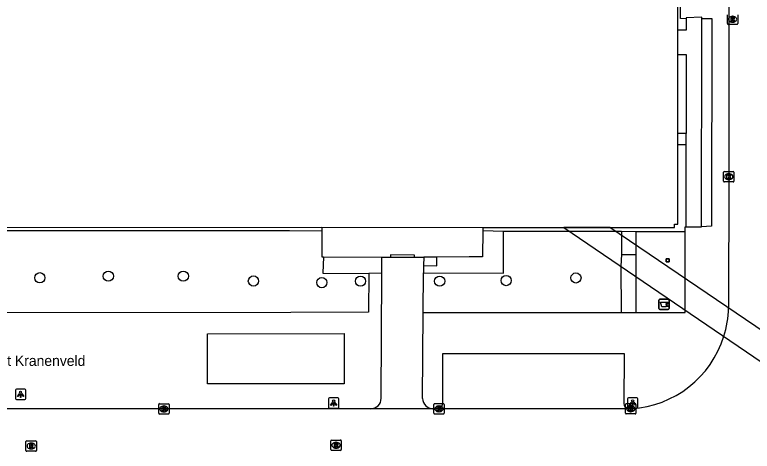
# Model space of a CAD drawing. Extents: x 161477 to 163040, y 383680 to 384868.
# Drawn here: x 161890.4 to 161961.2, y 384115.1 to 384157 of the extents above; entities that cross this region are included whole.
import ezdxf

# ---------------------------------------------------------------- set-up
doc = ezdxf.new("R2010")
doc.units = 0
for name, color, linetype in [('IMGEO_Afvalbak', 7, 'Continuous'), ('IMGEO_Boom', 7, 'Continuous'), ('IMGEO_Dek', 7, 'Continuous'), ('IMGEO_Groenvoorziening', 7, 'Continuous'), ('IMGEO_Kolk', 7, 'Continuous'), ('IMGEO_Lage_trafo', 7, 'Continuous'), ('IMGEO_Lichtpunt', 7, 'Continuous'), ('IMGEO_Openbare_ruimte_label', 7, 'Continuous'), ('IMGEO_Pand', 7, 'Continuous'), ('IMGEO_Pijler', 7, 'Continuous'), ('IMGEO_Rijbaan_lokaal_gesloten', 7, 'Continuous'), ('IMGEO_Rijbaan_lokaal_open', 7, 'Continuous'), ('IMGEO_Rioolput', 7, 'Continuous'), ('IMGEO_Terreindeel_halfverhard', 7, 'Continuous'), ('IMGEO_Voetpad_gesloten', 7, 'Continuous'), ('IMGEO_Voetpad_op_trap', 7, 'Continuous'), ('IMGEO_Voetpad_open', 7, 'Continuous')]:
    doc.layers.add(name, color=color, linetype=linetype)

msp = doc.modelspace()

# ---------------------------------------------------------------- linework, layer by layer
at = {"layer": 'IMGEO_Afvalbak'}
for p, q in [((161952.272, 384128.83), (161952.272, 384129.63)), ((161952.272, 384129.63), (161952.272, 384128.83)), ((161952.372, 384129.73), (161953.162, 384129.73)), ((161953.162, 384129.73), (161952.372, 384129.73)), ((161953.262, 384129.63), (161953.262, 384128.83)), ((161953.262, 384128.83), (161953.262, 384129.63)), ((161953.162, 384128.73), (161952.372, 384128.73)), ((161952.372, 384128.73), (161953.162, 384128.73))]:
    msp.add_line(p, q, dxfattribs=at)
msp.add_lwpolyline([(161952.415, 384129.444), (161953.119, 384129.444), (161952.97, 384128.974), (161952.564, 384128.974), (161952.415, 384129.444)], dxfattribs=at)
for centre, start, end in [((161952.372, 384129.63), 90, 180), ((161952.372, 384129.63), 90, 180), ((161953.162, 384129.63), 0, 90), ((161953.162, 384129.63), 360, 90), ((161952.372, 384128.83), 180, 270), ((161952.372, 384128.83), 180, 270), ((161953.162, 384128.83), 270, 0), ((161953.162, 384128.83), 270, 0)]:
    msp.add_arc(centre, 0.1, start, end, dxfattribs=at)
at = {"layer": 'IMGEO_Boom'}
for centre in [(161892.822, 384131.776), (161899.399, 384131.933), (161906.601, 384131.933), (161937.613, 384131.503), (161944.308, 384131.754), (161913.334, 384131.463), (161919.911, 384131.306), (161923.619, 384131.452), (161931.22, 384131.452)]:
    msp.add_circle(centre, 0.489, dxfattribs=at)
at = {"layer": 'IMGEO_Dek'}
msp.add_lwpolyline([(161947.548, 384136.601), (161943.149, 384136.604), (161969.026, 384119.003), (161969.032, 384122.037)], close=True, dxfattribs=at)
at = {"layer": 'IMGEO_Groenvoorziening'}
for points in [[(161870.773, 384136.302), (161876.802, 384136.301), (161879.272, 384136.301), (161916.787, 384136.298), (161919.889, 384136.28)], [(161929.655, 384132.234), (161937.363, 384132.218), (161937.349, 384136.252)], [(161937.349, 384136.252), (161943.684, 384136.24), (161948.093, 384136.231), (161948.689, 384136.23)], [(161950.049, 384136.227), (161954.784, 384136.218)], [(161920.067, 384133.782), (161920.015, 384132.225), (161924.432, 384132.187)], [(161952.977, 384133.298), (161952.983, 384133.587), (161953.272, 384133.581), (161953.266, 384133.292), (161952.977, 384133.298)], [(161953.265, 384129.319), (161953.27, 384129.041), (161952.992, 384129.036), (161952.987, 384129.314), (161953.265, 384129.319)]]:
    msp.add_lwpolyline(points, dxfattribs=at)
at = {"layer": 'IMGEO_Kolk'}
for p, q in [((161958.484, 384141.044), (161958.484, 384141.896)), ((161958.559, 384141.97), (161959.411, 384141.97)), ((161959.485, 384141.896), (161959.485, 384141.044)), ((161958.995, 384141.19), (161958.97, 384141.19)), ((161958.972, 384141.75), (161958.997, 384141.75)), ((161959.411, 384140.97), (161958.559, 384140.97)), ((161904.241, 384118.765), (161904.241, 384119.617)), ((161904.316, 384119.691), (161905.168, 384119.691)), ((161904.729, 384119.471), (161904.754, 384119.471)), ((161905.242, 384119.617), (161905.242, 384118.765)), ((161930.657, 384118.77), (161930.657, 384119.622)), ((161930.732, 384119.696), (161931.584, 384119.696)), ((161931.145, 384119.476), (161931.17, 384119.476)), ((161931.658, 384119.622), (161931.658, 384118.77)), ((161949.069, 384118.774), (161949.069, 384119.626)), ((161949.144, 384119.7), (161949.996, 384119.7)), ((161949.557, 384119.48), (161949.582, 384119.48)), ((161950.07, 384119.626), (161950.07, 384118.774)), ((161905.168, 384118.691), (161904.316, 384118.691)), ((161904.752, 384118.911), (161904.727, 384118.911)), ((161931.584, 384118.696), (161930.732, 384118.696)), ((161931.168, 384118.916), (161931.143, 384118.916)), ((161949.996, 384118.7), (161949.144, 384118.7)), ((161949.58, 384118.92), (161949.555, 384118.92))]:
    msp.add_line(p, q, dxfattribs=at)
for points in [[(161958.484, 384141.044), (161958.484, 384141.896)], [(161958.559, 384141.97), (161959.411, 384141.97)], [(161959.485, 384141.896), (161959.485, 384141.044)], [(161958.805, 384141.67), (161958.928, 384141.67), (161958.928, 384141.519), (161959.058, 384141.67), (161959.222, 384141.67), (161959.076, 384141.519), (161959.229, 384141.27), (161959.077, 384141.27), (161958.992, 384141.434), (161958.928, 384141.367), (161958.928, 384141.27), (161958.805, 384141.27), (161958.805, 384141.67)], [(161959.411, 384140.97), (161958.559, 384140.97)], [(161904.241, 384118.765), (161904.241, 384119.617)], [(161904.316, 384119.691), (161905.168, 384119.691)], [(161904.562, 384119.391), (161904.685, 384119.391), (161904.685, 384119.24), (161904.815, 384119.391), (161904.979, 384119.391), (161904.833, 384119.24), (161904.986, 384118.991), (161904.834, 384118.991), (161904.749, 384119.155), (161904.685, 384119.088), (161904.685, 384118.991), (161904.562, 384118.991), (161904.562, 384119.391)], [(161905.242, 384119.617), (161905.242, 384118.765)], [(161930.657, 384118.77), (161930.657, 384119.622)], [(161930.732, 384119.696), (161931.584, 384119.696)], [(161930.978, 384119.396), (161931.101, 384119.396), (161931.101, 384119.245), (161931.231, 384119.396), (161931.395, 384119.396), (161931.249, 384119.245), (161931.402, 384118.996), (161931.25, 384118.996), (161931.165, 384119.16), (161931.101, 384119.093), (161931.101, 384118.996), (161930.978, 384118.996), (161930.978, 384119.396)], [(161931.658, 384119.622), (161931.658, 384118.77)], [(161949.069, 384118.774), (161949.069, 384119.626)], [(161949.144, 384119.7), (161949.996, 384119.7)], [(161949.39, 384119.4), (161949.513, 384119.4), (161949.513, 384119.249), (161949.643, 384119.4), (161949.807, 384119.4), (161949.661, 384119.249), (161949.814, 384119), (161949.662, 384119), (161949.577, 384119.164), (161949.513, 384119.097), (161949.513, 384119), (161949.39, 384119), (161949.39, 384119.4)], [(161950.07, 384119.626), (161950.07, 384118.774)], [(161905.168, 384118.691), (161904.316, 384118.691)], [(161931.584, 384118.696), (161930.732, 384118.696)], [(161949.996, 384118.7), (161949.144, 384118.7)]]:
    msp.add_lwpolyline(points, dxfattribs=at)
for centre, start, end in [((161958.561, 384141.894), 91.55205, 178.44795), ((161958.561, 384141.894), 91.55205, 178.44795), ((161959.409, 384141.894), 1.55205, 88.44795), ((161959.409, 384141.894), 1.55205, 88.44795), ((161958.561, 384141.046), 181.55205, 268.44795), ((161958.561, 384141.046), 181.55205, 268.44795), ((161959.409, 384141.046), 271.55205, 358.44795), ((161959.409, 384141.046), 271.55205, 358.44795), ((161904.318, 384119.615), 91.55205, 178.44795), ((161904.318, 384119.615), 91.55205, 178.44795), ((161905.166, 384119.615), 1.55205, 88.44795), ((161905.166, 384119.615), 1.55205, 88.44795), ((161930.734, 384119.62), 91.55205, 178.44795), ((161930.734, 384119.62), 91.55205, 178.44795), ((161931.582, 384119.62), 1.55205, 88.44795), ((161931.582, 384119.62), 1.55205, 88.44795), ((161949.146, 384119.624), 91.55205, 178.44795), ((161949.146, 384119.624), 91.55205, 178.44795), ((161949.994, 384119.624), 1.55205, 88.44795), ((161949.994, 384119.624), 1.55205, 88.44795), ((161904.318, 384118.767), 181.55205, 268.44795), ((161904.318, 384118.767), 181.55205, 268.44795), ((161905.166, 384118.767), 271.55205, 358.44795), ((161905.166, 384118.767), 271.55205, 358.44795), ((161930.734, 384118.772), 181.55205, 268.44795), ((161930.734, 384118.772), 181.55205, 268.44795), ((161931.582, 384118.772), 271.55205, 358.44795), ((161931.582, 384118.772), 271.55205, 358.44795), ((161949.146, 384118.776), 181.55205, 268.44795), ((161949.146, 384118.776), 181.55205, 268.44795), ((161949.994, 384118.776), 271.55205, 358.44795), ((161949.994, 384118.776), 271.55205, 358.44795)]:
    msp.add_arc(centre, 0.0765, start, end, dxfattribs=at)
for centre, major_axis, ratio, start_param, end_param in [((161958.971, 384141.47), (-0.387, 0.002), 0.722429, 4.712389, 7.853982), ((161958.996, 384141.47), (-0.39, 0.002), 0.717154, 1.570796, 4.712389), ((161904.728, 384119.191), (-0.387, 0.002), 0.722429, 4.712389, 7.853982), ((161904.753, 384119.191), (-0.39, 0.002), 0.717154, 1.570796, 4.712389), ((161931.144, 384119.196), (-0.387, 0.002), 0.722429, 4.712389, 7.853982), ((161931.169, 384119.196), (-0.39, 0.002), 0.717154, 1.570796, 4.712389), ((161949.556, 384119.2), (-0.387, 0.002), 0.722429, 4.712389, 7.853982), ((161949.581, 384119.2), (-0.39, 0.002), 0.717154, 1.570796, 4.712389)]:
    msp.add_ellipse(centre, major_axis=major_axis, ratio=ratio, start_param=start_param, end_param=end_param, dxfattribs=at)
at = {"layer": 'IMGEO_Lage_trafo'}
msp.add_lwpolyline([(161908.935, 384126.404), (161922.043, 384126.414), (161922.035, 384121.601), (161908.927, 384121.591), (161908.935, 384126.404)], dxfattribs=at)
at = {"layer": 'IMGEO_Lichtpunt'}
for p, q in [((161890.476, 384120.991), (161890.476, 384120.184)), ((161890.476, 384120.991), (161890.476, 384120.184)), ((161891.378, 384121.086), (161890.57, 384121.086)), ((161891.378, 384121.086), (161890.57, 384121.086)), ((161891.472, 384120.184), (161891.472, 384120.991)), ((161891.472, 384120.184), (161891.472, 384120.991)), ((161890.57, 384120.09), (161891.378, 384120.09)), ((161890.57, 384120.09), (161891.378, 384120.09)), ((161920.539, 384120.148), (161920.539, 384119.341)), ((161920.539, 384120.148), (161920.539, 384119.341)), ((161921.441, 384120.243), (161920.633, 384120.243)), ((161921.441, 384120.243), (161920.633, 384120.243)), ((161921.535, 384119.341), (161921.535, 384120.148)), ((161921.535, 384119.341), (161921.535, 384120.148)), ((161949.253, 384120.16), (161949.253, 384119.353)), ((161949.253, 384120.16), (161949.253, 384119.353)), ((161950.155, 384120.255), (161949.347, 384120.255)), ((161950.155, 384120.255), (161949.347, 384120.255)), ((161950.249, 384119.353), (161950.249, 384120.16)), ((161950.249, 384119.353), (161950.249, 384120.16)), ((161920.633, 384119.247), (161921.441, 384119.247)), ((161920.633, 384119.247), (161921.441, 384119.247)), ((161949.347, 384119.259), (161950.155, 384119.259)), ((161949.347, 384119.259), (161950.155, 384119.259))]:
    msp.add_line(p, q, dxfattribs=at)
for points in [[(161890.85, 384120.655), (161890.889, 384120.627), (161890.701, 384120.365), (161890.663, 384120.392), (161890.85, 384120.655)], [(161891.062, 384120.627), (161891.1, 384120.654), (161891.287, 384120.392), (161891.248, 384120.364), (161891.062, 384120.627)], [(161890.952, 384120.607), (161890.999, 384120.607), (161890.999, 384120.285), (161890.952, 384120.285), (161890.952, 384120.607)], [(161920.913, 384119.812), (161920.952, 384119.784), (161920.764, 384119.522), (161920.726, 384119.549), (161920.913, 384119.812)], [(161921.015, 384119.764), (161921.062, 384119.764), (161921.062, 384119.442), (161921.015, 384119.442), (161921.015, 384119.764)], [(161921.125, 384119.784), (161921.163, 384119.811), (161921.35, 384119.549), (161921.311, 384119.521), (161921.125, 384119.784)], [(161949.627, 384119.824), (161949.666, 384119.796), (161949.478, 384119.534), (161949.44, 384119.561), (161949.627, 384119.824)], [(161949.729, 384119.776), (161949.776, 384119.776), (161949.776, 384119.454), (161949.729, 384119.454), (161949.729, 384119.776)], [(161949.839, 384119.796), (161949.877, 384119.823), (161950.064, 384119.561), (161950.025, 384119.533), (161949.839, 384119.796)]]:
    msp.add_lwpolyline(points, dxfattribs=at)
for centre in [(161890.975, 384120.789), (161921.038, 384119.946), (161949.752, 384119.958)]:
    msp.add_circle(centre, 0.0994, dxfattribs=at)
for centre, start, end in [((161890.57, 384120.991), 90, 180), ((161890.57, 384120.991), 90, 180), ((161891.378, 384120.991), 0, 90), ((161891.378, 384120.991), 0, 90), ((161890.57, 384120.184), 180, 270), ((161890.57, 384120.184), 180, 270), ((161891.378, 384120.184), 270, 0), ((161891.378, 384120.184), 270, 360), ((161920.633, 384120.148), 90, 180), ((161920.633, 384120.148), 90, 180), ((161921.441, 384120.148), 0, 90), ((161921.441, 384120.148), 0, 90), ((161949.347, 384120.16), 90, 180), ((161949.347, 384120.16), 90, 180), ((161950.155, 384120.16), 0, 90), ((161950.155, 384120.16), 0, 90), ((161920.633, 384119.341), 180, 270), ((161920.633, 384119.341), 180, 270), ((161921.441, 384119.341), 270, 0), ((161921.441, 384119.341), 270, 360), ((161949.347, 384119.353), 180, 270), ((161949.347, 384119.353), 180, 270), ((161950.155, 384119.353), 270, 0), ((161950.155, 384119.353), 270, 360)]:
    msp.add_arc(centre, 0.0946, start, end, dxfattribs=at)
at = {"layer": 'IMGEO_Pand'}
for points in [[(161954.094, 384155.541), (161954.075, 384175.873), (161947.567, 384175.873), (161947.467, 384175.873), (161947.367, 384175.873), (161945.027, 384175.873), (161926.299, 384175.874)], [(161954.094, 384153.206), (161954.094, 384155.541)], [(161954.094, 384145.628), (161954.094, 384153.206)], [(161871.434, 384150.746), (161871.439, 384144.431), (161871.441, 384142.039), (161871.446, 384136.601), (161876.803, 384136.603), (161879.273, 384136.604), (161919.889, 384136.62)], [(161954.094, 384144.533), (161954.094, 384145.628)], [(161935.366, 384136.609), (161943.147, 384136.604), (161947.548, 384136.601), (161950.002, 384136.599), (161953.774, 384136.607), (161953.774, 384136.927), (161954.094, 384136.927), (161954.094, 384144.533)], [(161919.889, 384136.62), (161935.366, 384136.609)]]:
    msp.add_lwpolyline(points, dxfattribs=at)
at = {"layer": 'IMGEO_Pijler'}
for points in [[(161953.266, 384133.292), (161953.272, 384133.581), (161952.983, 384133.587), (161952.977, 384133.298)], [(161953.27, 384129.041), (161953.265, 384129.319), (161952.987, 384129.314), (161952.992, 384129.036)]]:
    msp.add_lwpolyline(points, close=True, dxfattribs=at)
at = {"layer": 'IMGEO_Rijbaan_lokaal_gesloten'}
for points in [[(161925.658, 384133.765), (161926.499, 384133.761)], [(161925.664, 384132.213), (161925.658, 384133.765)], [(161926.499, 384133.761), (161928.815, 384133.757)], [(161928.815, 384133.757), (161929.685, 384133.755)], [(161929.685, 384133.755), (161929.66, 384132.942)], [(161929.66, 384132.942), (161929.655, 384132.234)], [(161925.603, 384120.203), (161925.664, 384132.213)], [(161929.628, 384128.456), (161929.655, 384132.234)], [(161929.58, 384120.179), (161929.628, 384128.456)], [(161930.575, 384119.21), (161924.611, 384119.191)]]:
    msp.add_lwpolyline(points, dxfattribs=at)
for centre, radius, start, end in [((161924.58, 384120.214), 1.023, 271.75125, 359.39234), ((161930.581, 384120.211), 1.001, 181.83441, 269.6825)]:
    msp.add_arc(centre, radius, start, end, dxfattribs=at)
at = {"layer": 'IMGEO_Rijbaan_lokaal_open'}
for points in [[(161958.979, 384172.665), (161958.985, 384141.471), (161958.97, 384128.881)], [(161924.611, 384119.191), (161907.804, 384119.203), (161907.646, 384119.202), (161904.742, 384119.192), (161882.894, 384119.196), (161880.154, 384119.146), (161880.064, 384119.146), (161879.209, 384119.143), (161876.743, 384119.134), (161867.138, 384119.099)], [(161931.139, 384119.201), (161931.035, 384119.201), (161930.575, 384119.21)], [(161949.26, 384119.206), (161931.139, 384119.201)], [(161949.647, 384119.202), (161949.401, 384119.206), (161949.26, 384119.206)]]:
    msp.add_lwpolyline(points, dxfattribs=at)
for centre, radius, start, end in [((161948.999, 384129.146), 9.974, 342.54058, 358.48028), ((161949.009, 384129.147), 9.965, 273.66995, 342.51712)]:
    msp.add_arc(centre, radius, start, end, dxfattribs=at)
at = {"layer": 'IMGEO_Rioolput'}
for p, q in [((161958.85, 384156.162), (161958.85, 384157.014)), ((161959.338, 384156.868), (161959.363, 384156.868)), ((161959.851, 384157.014), (161959.851, 384156.162)), ((161959.777, 384156.088), (161958.925, 384156.088)), ((161959.361, 384156.308), (161959.336, 384156.308)), ((161891.491, 384115.2), (161891.491, 384116.052)), ((161891.566, 384116.126), (161892.418, 384116.126)), ((161891.979, 384115.906), (161892.004, 384115.906)), ((161892.492, 384116.052), (161892.492, 384115.2)), ((161920.767, 384115.278), (161920.767, 384116.13)), ((161920.842, 384116.204), (161921.694, 384116.204)), ((161921.255, 384115.984), (161921.28, 384115.984)), ((161921.768, 384116.13), (161921.768, 384115.278)), ((161892.418, 384115.126), (161891.566, 384115.126)), ((161892.002, 384115.346), (161891.977, 384115.346)), ((161921.694, 384115.204), (161920.842, 384115.204)), ((161921.278, 384115.424), (161921.253, 384115.424))]:
    msp.add_line(p, q, dxfattribs=at)
for points in [[(161958.85, 384156.162), (161958.85, 384157.014)], [(161959.439, 384156.786), (161959.187, 384156.788), (161959.187, 384156.388)], [(161959.851, 384157.014), (161959.851, 384156.162)], [(161959.777, 384156.088), (161958.925, 384156.088)], [(161959.187, 384156.388), (161959.311, 384156.388), (161959.311, 384156.55), (161959.322, 384156.55)], [(161959.365, 384156.707), (161959.311, 384156.707), (161959.311, 384156.626)], [(161959.311, 384156.626), (161959.363, 384156.626)], [(161959.369, 384156.521), (161959.44, 384156.388), (161959.58, 384156.388), (161959.515, 384156.514)], [(161891.491, 384115.2), (161891.491, 384116.052)], [(161891.566, 384116.126), (161892.418, 384116.126)], [(161892.08, 384115.824), (161891.828, 384115.826), (161891.828, 384115.426)], [(161892.006, 384115.745), (161891.952, 384115.745), (161891.952, 384115.664)], [(161892.492, 384116.052), (161892.492, 384115.2)], [(161920.767, 384115.278), (161920.767, 384116.13)], [(161920.842, 384116.204), (161921.694, 384116.204)], [(161921.356, 384115.902), (161921.104, 384115.904), (161921.104, 384115.504)], [(161921.282, 384115.823), (161921.228, 384115.823), (161921.228, 384115.742)], [(161921.228, 384115.742), (161921.28, 384115.742)], [(161921.768, 384116.13), (161921.768, 384115.278)], [(161892.418, 384115.126), (161891.566, 384115.126)], [(161891.828, 384115.426), (161891.952, 384115.426), (161891.952, 384115.588), (161891.963, 384115.588)], [(161891.952, 384115.664), (161892.004, 384115.664)], [(161892.01, 384115.559), (161892.081, 384115.426), (161892.221, 384115.426), (161892.156, 384115.552)], [(161921.694, 384115.204), (161920.842, 384115.204)], [(161921.104, 384115.504), (161921.228, 384115.504), (161921.228, 384115.666), (161921.239, 384115.666)], [(161921.286, 384115.637), (161921.357, 384115.504), (161921.497, 384115.504), (161921.432, 384115.63)]]:
    msp.add_lwpolyline(points, dxfattribs=at)
for centre, radius, start, end in [((161959.438, 384156.676), 0.109, 350.36119, 89.41601), ((161958.927, 384156.164), 0.0765, 181.55205, 268.44795), ((161958.927, 384156.164), 0.0765, 181.55205, 268.44795), ((161959.321, 384156.497), 0.0533, 26.02933, 88.69889), ((161959.347, 384156.815), 0.19, 274.7715, 282.96867), ((161959.371, 384156.611), 0.0964, 77.00612, 93.18647), ((161959.385, 384156.668), 0.0378, 276.66336, 79.67722), ((161959.436, 384156.676), 0.112, 277.58423, 350.98172), ((161959.42, 384156.461), 0.108, 29.51342, 73.79051), ((161959.775, 384156.164), 0.0765, 271.55205, 358.44795), ((161959.775, 384156.164), 0.0765, 271.55205, 358.44795), ((161891.568, 384116.05), 0.0765, 91.55205, 178.44795), ((161891.568, 384116.05), 0.0765, 91.55205, 178.44795), ((161892.012, 384115.649), 0.0964, 77.00612, 93.18647), ((161892.026, 384115.706), 0.0378, 276.66336, 79.67722), ((161892.079, 384115.714), 0.109, 350.36119, 89.41601), ((161892.077, 384115.714), 0.112, 277.58423, 350.98172), ((161892.416, 384116.05), 0.0765, 1.55205, 88.44795), ((161892.416, 384116.05), 0.0765, 1.55205, 88.44795), ((161920.844, 384116.128), 0.0765, 91.55205, 178.44795), ((161920.844, 384116.128), 0.0765, 91.55205, 178.44795), ((161921.264, 384115.931), 0.19, 274.7715, 282.96867), ((161921.288, 384115.727), 0.0964, 77.00612, 93.18647), ((161921.302, 384115.784), 0.0378, 276.66336, 79.67722), ((161921.355, 384115.792), 0.109, 350.36119, 89.41601), ((161921.353, 384115.792), 0.112, 277.58423, 350.98172), ((161921.337, 384115.577), 0.108, 29.51342, 73.79051), ((161921.692, 384116.128), 0.0765, 1.55205, 88.44795), ((161921.692, 384116.128), 0.0765, 1.55205, 88.44795), ((161891.568, 384115.202), 0.0765, 181.55205, 268.44795), ((161891.568, 384115.202), 0.0765, 181.55205, 268.44795), ((161891.962, 384115.535), 0.0533, 26.02933, 88.69889), ((161891.988, 384115.853), 0.19, 274.7715, 282.96867), ((161892.061, 384115.499), 0.108, 29.51342, 73.79051), ((161892.416, 384115.202), 0.0765, 271.55205, 358.44795), ((161892.416, 384115.202), 0.0765, 271.55205, 358.44795), ((161920.844, 384115.28), 0.0765, 181.55205, 268.44795), ((161920.844, 384115.28), 0.0765, 181.55205, 268.44795), ((161921.238, 384115.613), 0.0533, 26.02933, 88.69889), ((161921.692, 384115.28), 0.0765, 271.55205, 358.44795), ((161921.692, 384115.28), 0.0765, 271.55205, 358.44795)]:
    msp.add_arc(centre, radius, start, end, dxfattribs=at)
for centre, major_axis, ratio, start_param, end_param in [((161959.337, 384156.588), (-0.387, 0.002), 0.722429, 4.712389, 7.853982), ((161959.362, 384156.588), (-0.39, 0.002), 0.717154, 1.570796, 4.712389), ((161891.978, 384115.626), (-0.387, 0.002), 0.722429, 4.712389, 7.853982), ((161892.003, 384115.626), (-0.39, 0.002), 0.717154, 1.570796, 4.712389), ((161921.254, 384115.704), (-0.387, 0.002), 0.722429, 4.712389, 7.853982), ((161921.279, 384115.704), (-0.39, 0.002), 0.717154, 1.570796, 4.712389)]:
    msp.add_ellipse(centre, major_axis=major_axis, ratio=ratio, start_param=start_param, end_param=end_param, dxfattribs=at)
at = {"layer": 'IMGEO_Terreindeel_halfverhard'}
msp.add_lwpolyline([(161935.362, 384136.294), (161937.349, 384136.252)], dxfattribs=at)
at = {"layer": 'IMGEO_Voetpad_gesloten'}
for points in [[(161956.397, 384156.656), (161956.394, 384156.768), (161954.884, 384156.729), (161954.887, 384156.609)], [(161954.887, 384156.609), (161954.89, 384155.541), (161954.094, 384155.541)], [(161956.381, 384136.66), (161956.391, 384155.536), (161956.397, 384156.656)], [(161954.094, 384153.206), (161954.9, 384153.211), (161954.888, 384145.634)], [(161954.888, 384145.634), (161954.094, 384145.628)], [(161954.9, 384144.533), (161954.888, 384145.634)], [(161954.9, 384144.533), (161954.094, 384144.533)], [(161954.883, 384136.656), (161954.9, 384144.533)], [(161919.889, 384136.62), (161919.889, 384136.28)], [(161919.889, 384136.28), (161919.897, 384133.781), (161920.067, 384133.782)], [(161935.362, 384136.294), (161935.342, 384133.781), (161934.041, 384133.792), (161930.945, 384133.76)], [(161935.366, 384136.609), (161935.362, 384136.294)], [(161947.548, 384136.601), (161943.149, 384136.604), (161969.026, 384119.003), (161969.032, 384121.788), (161969.032, 384122.037), (161947.548, 384136.601)], [(161954.883, 384136.656), (161956.381, 384136.66)], [(161920.067, 384133.782), (161925.658, 384133.765)], [(161928.815, 384133.757), (161928.816, 384133.957), (161926.5, 384133.971), (161926.499, 384133.761)], [(161929.66, 384132.942), (161930.955, 384132.918), (161930.945, 384133.76)], [(161930.945, 384133.76), (161929.685, 384133.755)]]:
    msp.add_lwpolyline(points, dxfattribs=at)
at = {"layer": 'IMGEO_Voetpad_op_trap'}
for points in [[(161948.689, 384136.23), (161948.687, 384135.827), (161948.677, 384134.009)], [(161948.689, 384136.23), (161950.049, 384136.227)], [(161950.049, 384136.227), (161950.049, 384134.905), (161950.049, 384134.003)]]:
    msp.add_lwpolyline(points, dxfattribs=at)
at = {"layer": 'IMGEO_Voetpad_open'}
for points in [[(161954.887, 384156.609), (161954.358, 384156.654), (161954.359, 384159.262)], [(161956.397, 384156.656), (161957.343, 384156.67), (161957.332, 384136.721), (161956.381, 384136.66)], [(161924.432, 384132.187), (161924.395, 384128.462), (161916.936, 384128.444), (161879.243, 384128.424), (161876.775, 384128.422), (161870.762, 384128.419), (161870.773, 384136.302)], [(161950.048, 384128.451), (161954.783, 384128.433), (161954.783, 384128.69), (161954.784, 384131.695), (161954.784, 384136.218)], [(161954.784, 384136.218), (161954.796, 384136.656), (161954.883, 384136.656)], [(161948.677, 384134.009), (161948.622, 384132.881), (161948.642, 384128.455)], [(161948.677, 384134.009), (161950.049, 384134.003)], [(161950.049, 384134.003), (161950.049, 384131.91), (161950.048, 384128.451)], [(161925.664, 384132.213), (161924.432, 384132.187)], [(161929.628, 384128.456), (161948.642, 384128.455)], [(161948.642, 384128.455), (161950.048, 384128.451)], [(161949.26, 384119.206), (161949.072, 384119.359), (161948.972, 384119.515), (161948.936, 384119.697), (161948.983, 384124.471), (161946.468, 384124.47), (161943.924, 384124.469), (161941.412, 384124.467), (161938.872, 384124.466), (161936.322, 384124.465), (161933.876, 384124.463), (161931.496, 384124.461), (161931.488, 384119.722), (161931.469, 384119.561), (161931.4, 384119.415), (161931.288, 384119.298), (161931.139, 384119.201)]]:
    msp.add_lwpolyline(points, dxfattribs=at)

# ---------------------------------------------------------------- texts
at = {"layer": 'IMGEO_Openbare_ruimte_label'}
msp.add_text('Het Kranenveld', height=1, dxfattribs=at).set_placement((161887.978, 384123.313))

doc.saveas('drawing.dxf')
